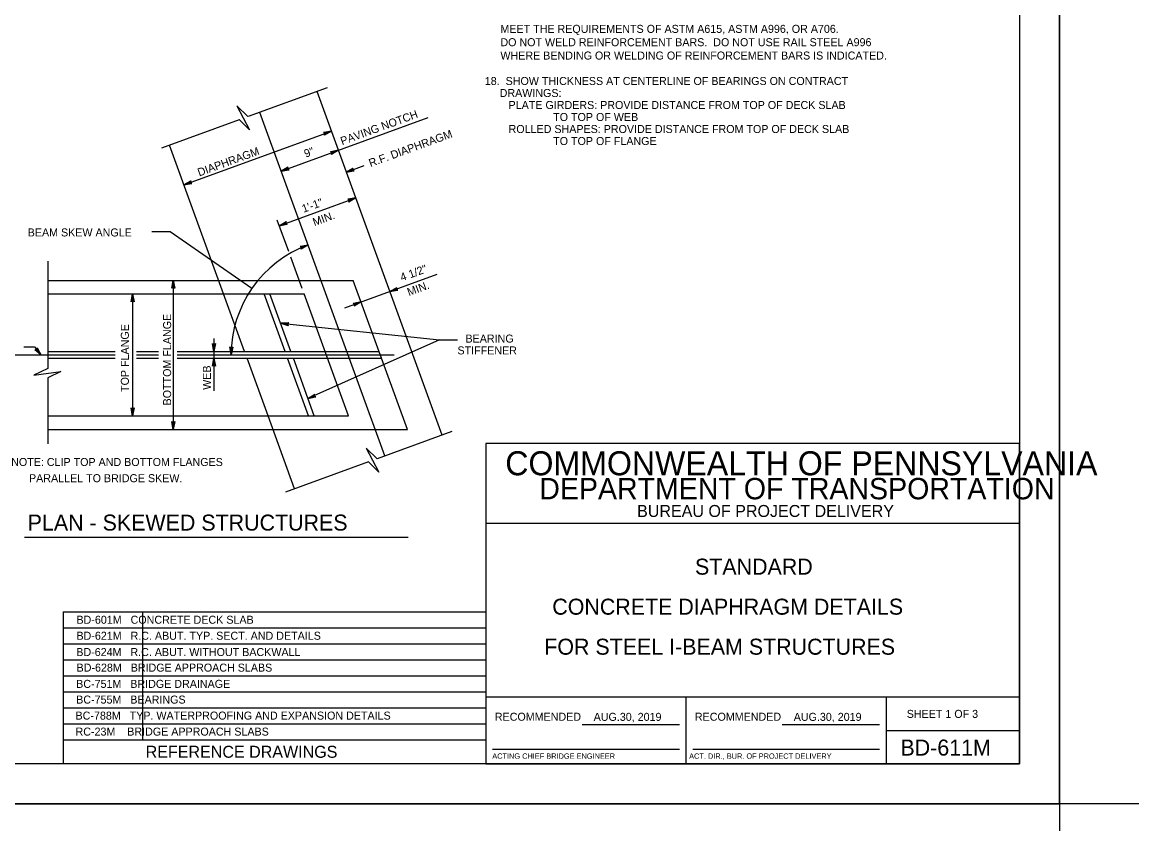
# Model space of a CAD drawing. Extents: x 640009 to 641706, y 298547 to 299735.
# Drawn here: x 640461.6 to 640877.6, y 299133.7 to 299434.1 of the extents above; entities that cross this region are included whole.
import ezdxf

# ---------------------------------------------------------------- set-up
doc = ezdxf.new("R2010")
doc.units = 0
doc.layers.add('1', color=7, linetype='Continuous')
doc.layers.add('PLT-BNDY', color=7, linetype='Continuous')

msp = doc.modelspace()

# ---------------------------------------------------------------- linework, layer by layer
at = {"layer": '1'}
for p, q in [((640835.47, 299720.17), (640835.47, 299156.17)), ((640835.47, 299720.17), (640835.47, 299156.17)), ((640576.01, 299409.55), (640546.3, 299398.74)), ((640619.01, 299279.35), (640572.14, 299408.14)), ((640597.53, 299271.53), (640550.66, 299400.32)), ((640542.93, 299397.51), (640513.87, 299386.93)), ((640558.67, 299378.31), (640613.85, 299398.39)), ((640522.26, 299373.17), (640577.54, 299393.29)), ((640537.14, 299332.28), (640516.86, 299388.02)), ((640583.14, 299377.91), (640589.88, 299380.37)), ((640558.01, 299357.83), (640586.65, 299368.26)), ((640561.54, 299348.14), (640557.26, 299359.9)), ((640510.22, 299355.67), (640517.07, 299355.67)), ((640517.07, 299355.67), (640547.76, 299334.38)), ((640566.57, 299334.31), (640562.29, 299346.07)), ((640471.19, 299344.51), (640471.19, 299304.37)), ((640471.19, 299337.36), (640585.73, 299337.36)), ((640518.25, 299337.36), (640518.25, 299281.48)), ((640582.58, 299327.02), (640617.22, 299339.63)), ((640606.07, 299281.48), (640585.73, 299337.36)), ((640471.19, 299332.28), (640567.31, 299332.28)), ((640503.01, 299332.28), (640503.01, 299286.56)), ((640545, 299310.69), (640537.14, 299332.28)), ((640560.21, 299310.69), (640552.36, 299332.28)), ((640562.34, 299310.69), (640554.48, 299332.28)), ((640583.95, 299286.56), (640567.31, 299332.28)), ((640558.49, 299321.27), (640618.01, 299315.12)), ((640462.19, 299312.44), (640466.19, 299312.44)), ((640466.19, 299312.44), (640468.66, 299309.42)), ((640533.49, 299315.6), (640533.49, 299295.92)), ((640618.01, 299315.12), (640568.76, 299293.07)), ((640618.01, 299315.12), (640624.86, 299315.12)), ((640446.9, 299309.42), (640496.46, 299309.42)), ((640471.19, 299310.69), (640496.46, 299310.69)), ((640471.19, 299308.15), (640496.46, 299308.15)), ((640504.48, 299310.69), (640512.71, 299310.69)), ((640504.48, 299309.42), (640512.71, 299309.42)), ((640504.48, 299308.15), (640512.71, 299308.15)), ((640519.73, 299310.69), (640575.17, 299310.69)), ((640519.73, 299309.42), (640601.1, 299309.42)), ((640519.73, 299308.15), (640576.09, 299308.15)), ((640553.79, 299286.56), (640545.93, 299308.15)), ((640569, 299286.56), (640561.14, 299308.15)), ((640571.13, 299286.56), (640563.27, 299308.15)), ((640575.17, 299310.69), (640595.44, 299310.69)), ((640576.09, 299308.15), (640596.37, 299308.15)), ((640471.19, 299300.85), (640471.19, 299276.08)), ((640471.19, 299286.56), (640583.95, 299286.56)), ((640563.73, 299259.23), (640553.79, 299286.56)), ((640471.19, 299281.48), (640606.07, 299281.48)), ((640622.74, 299280.71), (640594.72, 299270.51)), ((640835.47, 299276.17), (640635.47, 299276.17)), ((640635.47, 299276.17), (640635.47, 299156.17)), ((640835.47, 299276.17), (640635.47, 299276.17)), ((640635.47, 299276.17), (640635.47, 299156.17)), ((640835.47, 299156.17), (640835.47, 299276.17)), ((640835.47, 299156.17), (640835.47, 299276.17)), ((640591.41, 299269.31), (640560.39, 299258.01)), ((640835.47, 299246.17), (640635.47, 299246.17)), ((640835.47, 299246.17), (640635.47, 299246.17)), ((640462.55, 299241.16), (640606.33, 299241.16)), ((640477.04, 299213.17), (640477.04, 299156.17)), ((640477.04, 299213.17), (640635.47, 299213.17)), ((640506.91, 299165.17), (640506.91, 299213.17)), ((640477.04, 299207.17), (640635.47, 299207.17)), ((640477.04, 299201.17), (640635.47, 299201.17)), ((640477.04, 299195.17), (640635.47, 299195.17)), ((640477.04, 299189.17), (640635.47, 299189.17)), ((640477.04, 299183.17), (640635.47, 299183.17)), ((640835.47, 299181.17), (640635.47, 299181.17)), ((640835.47, 299181.17), (640635.47, 299181.17)), ((640710.47, 299156.17), (640710.47, 299181.17)), ((640785.47, 299181.17), (640785.47, 299156.17)), ((640785.47, 299181.17), (640785.47, 299156.17)), ((640477.04, 299177.17), (640635.47, 299177.17)), ((640477.04, 299171.17), (640635.47, 299171.17)), ((640671.56, 299170.89), (640707.97, 299170.89)), ((640746.56, 299170.89), (640782.97, 299170.89)), ((640785.47, 299168.67), (640835.47, 299168.67)), ((640785.47, 299168.67), (640835.47, 299168.67)), ((640477.04, 299165.17), (640635.47, 299165.17)), ((640637.97, 299161.67), (640707.97, 299161.67)), ((640712.97, 299161.67), (640782.97, 299161.67)), ((640835.47, 299156.17), (640049.47, 299156.17)), ((640835.47, 299156.17), (640049.47, 299156.17)), ((640635.47, 299156.17), (640835.47, 299156.17)), ((640635.47, 299156.17), (640835.47, 299156.17))]:
    msp.add_line(p, q, dxfattribs=at)
for points in [[(640546.21, 299398.83), (640542.05, 299402.83), (640546.82, 299393.77), (640542.9, 299397.62)], [(640577.54, 299393.29), (640574.93, 299391.74), (640575.01, 299391.85), (640575.09, 299391.97), (640575.11, 299392.08), (640575.14, 299392.2), (640575.12, 299392.3), (640575.1, 299392.4), (640575.05, 299392.48), (640575, 299392.57), (640574.91, 299392.65), (640574.82, 299392.72), (640574.68, 299392.76), (640574.55, 299392.79), (640577.54, 299393.29), (640574.68, 299392.76), (640574.82, 299392.72), (640577.54, 299393.29), (640574.91, 299392.65), (640575, 299392.57), (640577.54, 299393.29), (640575.05, 299392.48), (640575.1, 299392.4), (640577.54, 299393.29), (640575.12, 299392.3), (640575.14, 299392.2), (640577.54, 299393.29), (640575.11, 299392.08), (640575.09, 299391.97), (640577.54, 299393.29), (640575.01, 299391.85)], [(640580.15, 299386.12), (640577.54, 299384.58), (640577.62, 299384.69), (640577.7, 299384.81), (640577.72, 299384.92), (640577.74, 299385.04), (640577.72, 299385.14), (640577.71, 299385.24), (640577.66, 299385.32), (640577.61, 299385.41), (640577.52, 299385.49), (640577.43, 299385.56), (640577.29, 299385.59), (640577.16, 299385.63), (640580.15, 299386.12), (640577.29, 299385.59), (640577.43, 299385.56), (640580.15, 299386.12), (640577.52, 299385.49), (640577.61, 299385.41), (640580.15, 299386.12), (640577.66, 299385.32), (640577.71, 299385.24), (640580.15, 299386.12), (640577.72, 299385.14), (640577.74, 299385.04), (640580.15, 299386.12), (640577.72, 299384.92), (640577.7, 299384.81), (640580.15, 299386.12), (640577.62, 299384.69)], [(640558.67, 299378.31), (640561.28, 299379.85), (640561.2, 299379.74), (640561.12, 299379.62), (640561.1, 299379.51), (640561.07, 299379.4), (640561.09, 299379.3), (640561.11, 299379.2), (640561.16, 299379.11), (640561.21, 299379.02), (640561.3, 299378.95), (640561.39, 299378.87), (640561.53, 299378.84), (640561.66, 299378.8), (640558.67, 299378.31), (640561.53, 299378.84), (640561.39, 299378.87), (640558.67, 299378.31), (640561.3, 299378.95), (640561.21, 299379.02), (640558.67, 299378.31), (640561.16, 299379.11), (640561.11, 299379.2), (640558.67, 299378.31), (640561.09, 299379.3), (640561.07, 299379.4), (640558.67, 299378.31), (640561.1, 299379.51), (640561.12, 299379.62), (640558.67, 299378.31), (640561.2, 299379.74)], [(640583.14, 299377.91), (640585.75, 299379.46), (640585.67, 299379.35), (640585.59, 299379.23), (640585.57, 299379.12), (640585.54, 299379), (640585.56, 299378.9), (640585.58, 299378.8), (640585.63, 299378.72), (640585.68, 299378.63), (640585.77, 299378.55), (640585.86, 299378.48), (640586, 299378.44), (640586.13, 299378.41), (640583.14, 299377.91), (640586, 299378.44), (640585.86, 299378.48), (640583.14, 299377.91), (640585.77, 299378.55), (640585.68, 299378.63), (640583.14, 299377.91), (640585.63, 299378.72), (640585.58, 299378.8), (640583.14, 299377.91), (640585.56, 299378.9), (640585.54, 299379), (640583.14, 299377.91), (640585.57, 299379.12), (640585.59, 299379.23), (640583.14, 299377.91), (640585.67, 299379.35)], [(640522.26, 299373.17), (640524.88, 299374.71), (640524.8, 299374.6), (640524.71, 299374.48), (640524.69, 299374.37), (640524.67, 299374.25), (640524.69, 299374.15), (640524.71, 299374.05), (640524.76, 299373.97), (640524.81, 299373.88), (640524.9, 299373.8), (640524.99, 299373.73), (640525.12, 299373.7), (640525.26, 299373.66), (640522.26, 299373.17), (640525.12, 299373.7), (640524.99, 299373.73), (640522.26, 299373.17), (640524.9, 299373.8), (640524.81, 299373.88), (640522.26, 299373.17), (640524.76, 299373.97), (640524.71, 299374.05), (640522.26, 299373.17), (640524.69, 299374.15), (640524.67, 299374.25), (640522.26, 299373.17), (640524.69, 299374.37), (640524.71, 299374.48), (640522.26, 299373.17), (640524.8, 299374.6)], [(640586.65, 299368.26), (640584.04, 299366.71), (640584.12, 299366.83), (640584.2, 299366.94), (640584.22, 299367.06), (640584.25, 299367.17), (640584.23, 299367.27), (640584.21, 299367.37), (640584.16, 299367.46), (640584.11, 299367.55), (640584.02, 299367.62), (640583.93, 299367.69), (640583.79, 299367.73), (640583.66, 299367.76), (640586.65, 299368.26), (640583.79, 299367.73), (640583.93, 299367.69), (640586.65, 299368.26), (640584.02, 299367.62), (640584.11, 299367.55), (640586.65, 299368.26), (640584.16, 299367.46), (640584.21, 299367.37), (640586.65, 299368.26), (640584.23, 299367.27), (640584.25, 299367.17), (640586.65, 299368.26), (640584.22, 299367.06), (640584.2, 299366.94), (640586.65, 299368.26), (640584.12, 299366.83)], [(640558.01, 299357.83), (640560.62, 299359.38), (640560.54, 299359.27), (640560.46, 299359.15), (640560.44, 299359.04), (640560.42, 299358.92), (640560.44, 299358.82), (640560.45, 299358.72), (640560.5, 299358.63), (640560.55, 299358.55), (640560.64, 299358.47), (640560.73, 299358.4), (640560.87, 299358.36), (640561, 299358.33), (640558.01, 299357.83), (640560.87, 299358.36), (640560.73, 299358.4), (640558.01, 299357.83), (640560.64, 299358.47), (640560.55, 299358.55), (640558.01, 299357.83), (640560.5, 299358.63), (640560.45, 299358.72), (640558.01, 299357.83), (640560.44, 299358.82), (640560.42, 299358.92), (640558.01, 299357.83), (640560.44, 299359.04), (640560.46, 299359.15), (640558.01, 299357.83), (640560.54, 299359.27)], [(640568.76, 299350.57), (640566.15, 299349.03), (640566.23, 299349.14), (640566.31, 299349.26), (640566.33, 299349.37), (640566.35, 299349.48), (640566.34, 299349.58), (640566.32, 299349.68), (640566.27, 299349.77), (640566.22, 299349.86), (640566.13, 299349.93), (640566.04, 299350.01), (640565.9, 299350.04), (640565.77, 299350.08), (640568.76, 299350.57), (640565.9, 299350.04), (640566.04, 299350.01), (640568.76, 299350.57), (640566.13, 299349.93), (640566.22, 299349.86), (640568.76, 299350.57), (640566.27, 299349.77), (640566.32, 299349.68), (640568.76, 299350.57), (640566.34, 299349.58), (640566.35, 299349.48), (640568.76, 299350.57), (640566.33, 299349.37), (640566.31, 299349.26), (640568.76, 299350.57), (640566.23, 299349.14)], [(640518.25, 299337.36), (640518.81, 299334.38), (640518.73, 299334.49), (640518.65, 299334.61), (640518.55, 299334.67), (640518.45, 299334.73), (640518.35, 299334.74), (640518.25, 299334.76), (640518.15, 299334.74), (640518.05, 299334.73), (640517.95, 299334.67), (640517.85, 299334.61), (640517.77, 299334.49), (640517.69, 299334.38), (640518.25, 299337.36), (640517.77, 299334.49), (640517.85, 299334.61), (640518.25, 299337.36), (640517.95, 299334.67), (640518.05, 299334.73), (640518.25, 299337.36), (640518.15, 299334.74), (640518.25, 299334.76), (640518.25, 299337.36), (640518.35, 299334.74), (640518.45, 299334.73), (640518.25, 299337.36), (640518.55, 299334.67), (640518.65, 299334.61), (640518.25, 299337.36), (640518.73, 299334.49)], [(640599.43, 299333.15), (640602.04, 299334.7), (640601.96, 299334.59), (640601.88, 299334.47), (640601.86, 299334.36), (640601.84, 299334.24), (640601.85, 299334.14), (640601.87, 299334.04), (640601.92, 299333.96), (640601.97, 299333.87), (640602.06, 299333.79), (640602.15, 299333.72), (640602.29, 299333.68), (640602.42, 299333.65), (640599.43, 299333.15), (640602.29, 299333.68), (640602.15, 299333.72), (640599.43, 299333.15), (640602.06, 299333.79), (640601.97, 299333.87), (640599.43, 299333.15), (640601.92, 299333.96), (640601.87, 299334.04), (640599.43, 299333.15), (640601.85, 299334.14), (640601.84, 299334.24), (640599.43, 299333.15), (640601.86, 299334.36), (640601.88, 299334.47), (640599.43, 299333.15), (640601.96, 299334.59)], [(640503.01, 299332.28), (640503.57, 299329.3), (640503.49, 299329.42), (640503.41, 299329.53), (640503.31, 299329.59), (640503.21, 299329.65), (640503.11, 299329.67), (640503.01, 299329.68), (640502.91, 299329.67), (640502.81, 299329.65), (640502.71, 299329.59), (640502.61, 299329.53), (640502.53, 299329.42), (640502.45, 299329.3), (640503.01, 299332.28), (640502.53, 299329.42), (640502.61, 299329.53), (640503.01, 299332.28), (640502.71, 299329.59), (640502.81, 299329.65), (640503.01, 299332.28), (640502.91, 299329.67), (640503.01, 299329.68), (640503.01, 299332.28), (640503.11, 299329.67), (640503.21, 299329.65), (640503.01, 299332.28), (640503.31, 299329.59), (640503.41, 299329.53), (640503.01, 299332.28), (640503.49, 299329.42)], [(640588.69, 299329.25), (640586.08, 299327.7), (640586.16, 299327.81), (640586.24, 299327.93), (640586.26, 299328.04), (640586.28, 299328.16), (640586.26, 299328.26), (640586.25, 299328.36), (640586.19, 299328.44), (640586.14, 299328.53), (640586.05, 299328.61), (640585.96, 299328.68), (640585.83, 299328.72), (640585.69, 299328.75), (640588.69, 299329.25), (640585.83, 299328.72), (640585.96, 299328.68), (640588.69, 299329.25), (640586.05, 299328.61), (640586.14, 299328.53), (640588.69, 299329.25), (640586.19, 299328.44), (640586.25, 299328.36), (640588.69, 299329.25), (640586.26, 299328.26), (640586.28, 299328.16), (640588.69, 299329.25), (640586.26, 299328.04), (640586.24, 299327.93), (640588.69, 299329.25), (640586.16, 299327.81)], [(640558.49, 299321.27), (640561.52, 299321.48), (640561.4, 299321.41), (640561.27, 299321.34), (640561.2, 299321.25), (640561.13, 299321.16), (640561.11, 299321.06), (640561.08, 299320.96), (640561.08, 299320.86), (640561.09, 299320.76), (640561.13, 299320.66), (640561.18, 299320.55), (640561.29, 299320.46), (640561.39, 299320.37), (640558.49, 299321.27), (640561.29, 299320.46), (640561.18, 299320.55), (640558.49, 299321.27), (640561.13, 299320.66), (640561.09, 299320.76), (640558.49, 299321.27), (640561.08, 299320.86), (640561.08, 299320.96), (640558.49, 299321.27), (640561.11, 299321.06), (640561.13, 299321.16), (640558.49, 299321.27), (640561.2, 299321.25), (640561.27, 299321.34), (640558.49, 299321.27), (640561.4, 299321.41)], [(640468.66, 299309.42), (640466.34, 299311.37), (640466.47, 299311.34), (640466.61, 299311.3), (640466.72, 299311.31), (640466.84, 299311.33), (640466.93, 299311.38), (640467.01, 299311.43), (640467.08, 299311.51), (640467.15, 299311.59), (640467.19, 299311.69), (640467.23, 299311.8), (640467.22, 299311.94), (640467.2, 299312.08), (640468.66, 299309.42), (640467.22, 299311.94), (640467.23, 299311.8), (640468.66, 299309.42), (640467.19, 299311.69), (640467.15, 299311.59), (640468.66, 299309.42), (640467.08, 299311.51), (640467.01, 299311.43), (640468.66, 299309.42), (640466.93, 299311.38), (640466.84, 299311.33), (640468.66, 299309.42), (640466.72, 299311.31), (640466.61, 299311.3), (640468.66, 299309.42), (640466.47, 299311.34)], [(640533.49, 299310.69), (640532.93, 299313.67), (640533.01, 299313.56), (640533.09, 299313.44), (640533.19, 299313.38), (640533.29, 299313.33), (640533.39, 299313.31), (640533.49, 299313.29), (640533.59, 299313.31), (640533.69, 299313.33), (640533.79, 299313.38), (640533.89, 299313.44), (640533.97, 299313.56), (640534.05, 299313.67), (640533.49, 299310.69), (640533.97, 299313.56), (640533.89, 299313.44), (640533.49, 299310.69), (640533.79, 299313.38), (640533.69, 299313.33), (640533.49, 299310.69), (640533.59, 299313.31), (640533.49, 299313.29), (640533.49, 299310.69), (640533.39, 299313.31), (640533.29, 299313.33), (640533.49, 299310.69), (640533.19, 299313.38), (640533.09, 299313.44), (640533.49, 299310.69), (640533.01, 299313.56)], [(640539.95, 299309.42), (640539.48, 299312.42), (640539.55, 299312.3), (640539.63, 299312.18), (640539.73, 299312.12), (640539.82, 299312.06), (640539.92, 299312.04), (640540.02, 299312.02), (640540.12, 299312.03), (640540.22, 299312.05), (640540.33, 299312.1), (640540.43, 299312.16), (640540.51, 299312.27), (640540.59, 299312.38), (640539.95, 299309.42), (640540.51, 299312.27), (640540.43, 299312.16), (640539.95, 299309.42), (640540.33, 299312.1), (640540.22, 299312.05), (640539.95, 299309.42), (640540.12, 299312.03), (640540.02, 299312.02), (640539.95, 299309.42), (640539.92, 299312.04), (640539.82, 299312.06), (640539.95, 299309.42), (640539.73, 299312.12), (640539.63, 299312.18), (640539.95, 299309.42), (640539.55, 299312.3)], [(640533.49, 299308.15), (640534.05, 299305.17), (640533.97, 299305.28), (640533.89, 299305.4), (640533.79, 299305.46), (640533.69, 299305.51), (640533.59, 299305.53), (640533.49, 299305.55), (640533.39, 299305.53), (640533.29, 299305.51), (640533.19, 299305.46), (640533.09, 299305.4), (640533.01, 299305.28), (640532.93, 299305.17), (640533.49, 299308.15), (640533.01, 299305.28), (640533.09, 299305.4), (640533.49, 299308.15), (640533.19, 299305.46), (640533.29, 299305.51), (640533.49, 299308.15), (640533.39, 299305.53), (640533.49, 299305.55), (640533.49, 299308.15), (640533.59, 299305.53), (640533.69, 299305.51), (640533.49, 299308.15), (640533.79, 299305.46), (640533.89, 299305.4), (640533.49, 299308.15), (640533.97, 299305.28)], [(640471.19, 299304.37), (640466.01, 299301.83), (640476.15, 299303.21), (640471.19, 299300.85)], [(640568.76, 299293.07), (640571.3, 299294.73), (640571.22, 299294.61), (640571.15, 299294.49), (640571.13, 299294.38), (640571.11, 299294.26), (640571.14, 299294.16), (640571.16, 299294.06), (640571.21, 299293.98), (640571.27, 299293.89), (640571.36, 299293.82), (640571.45, 299293.75), (640571.59, 299293.72), (640571.73, 299293.69), (640568.76, 299293.07), (640571.59, 299293.72), (640571.45, 299293.75), (640568.76, 299293.07), (640571.36, 299293.82), (640571.27, 299293.89), (640568.76, 299293.07), (640571.21, 299293.98), (640571.16, 299294.06), (640568.76, 299293.07), (640571.14, 299294.16), (640571.11, 299294.26), (640568.76, 299293.07), (640571.13, 299294.38), (640571.15, 299294.49), (640568.76, 299293.07), (640571.22, 299294.61)], [(640503.01, 299286.56), (640502.45, 299289.54), (640502.53, 299289.42), (640502.61, 299289.31), (640502.71, 299289.25), (640502.81, 299289.19), (640502.91, 299289.17), (640503.01, 299289.16), (640503.11, 299289.17), (640503.21, 299289.19), (640503.31, 299289.25), (640503.41, 299289.31), (640503.49, 299289.42), (640503.57, 299289.54), (640503.01, 299286.56), (640503.49, 299289.42), (640503.41, 299289.31), (640503.01, 299286.56), (640503.31, 299289.25), (640503.21, 299289.19), (640503.01, 299286.56), (640503.11, 299289.17), (640503.01, 299289.16), (640503.01, 299286.56), (640502.91, 299289.17), (640502.81, 299289.19), (640503.01, 299286.56), (640502.71, 299289.25), (640502.61, 299289.31), (640503.01, 299286.56), (640502.53, 299289.42)], [(640518.25, 299281.48), (640517.69, 299284.46), (640517.77, 299284.35), (640517.85, 299284.23), (640517.95, 299284.17), (640518.05, 299284.11), (640518.15, 299284.1), (640518.25, 299284.08), (640518.35, 299284.1), (640518.45, 299284.11), (640518.55, 299284.17), (640518.65, 299284.23), (640518.73, 299284.35), (640518.81, 299284.46), (640518.25, 299281.48), (640518.73, 299284.35), (640518.65, 299284.23), (640518.25, 299281.48), (640518.55, 299284.17), (640518.45, 299284.11), (640518.25, 299281.48), (640518.35, 299284.1), (640518.25, 299284.08), (640518.25, 299281.48), (640518.15, 299284.1), (640518.05, 299284.11), (640518.25, 299281.48), (640517.95, 299284.17), (640517.85, 299284.23), (640518.25, 299281.48), (640517.77, 299284.35)], [(640594.72, 299270.51), (640590.56, 299274.51), (640595.33, 299265.45), (640591.41, 299269.31)]]:
    msp.add_lwpolyline(points, dxfattribs=at)
msp.add_arc((640583.74, 299309.42), 43.79, 110, 180, dxfattribs=at)
at = {"layer": 'PLT-BNDY'}
for points in [[(640009.47, 299735.17), (640850.47, 299735.17), (640850.47, 299141.17), (640009.47, 299141.17)], [(640850.47, 299735.17), (641691.47, 299735.17), (641691.47, 299141.17), (640850.47, 299141.17)], [(640009.47, 299141.17), (640850.47, 299141.17), (640850.47, 298547.17), (640009.47, 298547.17)]]:
    msp.add_lwpolyline(points, close=True, dxfattribs=at)

# ---------------------------------------------------------------- texts
at = {"layer": '1'}
for s, height, p in [('     MEET THE REQUIREMENTS OF ASTM A615, ASTM A996, OR A706.', 3, (640635.32, 299430.12)), ('     DO NOT WELD REINFORCEMENT BARS.  DO NOT USE RAIL STEEL A996', 3, (640635.32, 299425.12)), ('     WHERE BENDING OR WELDING OF REINFORCEMENT BARS IS INDICATED.', 3, (640635.32, 299420.12)), ('18.  SHOW THICKNESS AT CENTERLINE OF BEARINGS ON CONTRACT', 3, (640635.04, 299410.59)), ('     DRAWINGS:', 3, (640635.04, 299406.09)), ('        PLATE GIRDERS: PROVIDE DISTANCE FROM TOP OF DECK SLAB', 3, (640635.04, 299401.59)), ('                       TO TOP OF WEB', 3, (640635.04, 299397.09)), ('        ROLLED SHAPES: PROVIDE DISTANCE FROM TOP OF DECK SLAB', 3, (640635.04, 299392.59)), ('                       TO TOP OF FLANGE', 3, (640635.04, 299388.09)), ('BEAM SKEW ANGLE', 3, (640463.69, 299353.82)), ('BEARING', 3, (640627.8, 299314.04)), ('STIFFENER', 3, (640624.8, 299309.6)), ('NOTE: CLIP TOP AND BOTTOM FLANGES', 3, (640457.49, 299267.78)), ('COMMONWEALTH OF PENNSYLVANIA', 9, (640642.72, 299264.3)), ('      PARALLEL TO BRIDGE SKEW.', 3, (640457.49, 299261.71)), ('DEPARTMENT OF TRANSPORTATION', 8.0002, (640655.47, 299255.3)), ('PLAN - SKEWED STRUCTURES', 6, (640463.68, 299243.57)), ('BUREAU OF PROJECT DELIVERY', 4.5, (640692.13, 299248.67)), ('STANDARD', 6, (640713.84, 299227.05)), ('CONCRETE DIAPHRAGM DETAILS', 6, (640660.34, 299212.05)), ('BD-601M   CONCRETE DECK SLAB', 3, (640481.97, 299208.66)), ('BD-621M   R.C. ABUT. TYP. SECT. AND DETAILS', 3, (640481.97, 299202.66)), ('BD-624M   R.C. ABUT. WITHOUT BACKWALL', 3, (640481.91, 299196.55)), ('FOR STEEL I-BEAM STRUCTURES', 6, (640657.34, 299197.05)), ('BD-628M   BRIDGE APPROACH SLABS', 3, (640482.01, 299190.71)), ('BC-751M   BRIDGE DRAINAGE', 3, (640481.86, 299184.62)), ('BC-755M   BEARINGS', 3, (640481.86, 299178.73)), ('BC-788M   TYP. WATERPROOFING AND EXPANSION DETAILS', 3, (640481.62, 299172.73)), ('RECOMMENDED', 3, (640638.8, 299172.3)), ('AUG.30, 2019', 3, (640675.85, 299172.26)), ('RECOMMENDED', 3, (640713.8, 299172.3)), ('AUG.30, 2019', 3, (640750.85, 299172.26)), ('SHEET 1 OF 3', 3, (640793.21, 299173.37)), ('RC-23M    BRIDGE APPROACH SLABS', 3, (640481.62, 299166.73)), ('REFERENCE DRAWINGS', 4.5, (640507.91, 299158.42)), ('BD-611M', 6, (640790.86, 299159.24)), ('ACTING CHIEF BRIDGE ENGINEER', 2.0002, (640637.84, 299158.05)), (' ACT. DIR., BUR. OF PROJECT DELIVERY', 2.0002, (640710.87, 299158.05))]:
    msp.add_text(s, height=height, dxfattribs=at).set_placement(p)
for s, rotation, p in [('PAVING NOTCH', 20, (640581.56, 299388.01)), ('R.F. DIAPHRAGM', 20, (640592.2, 299379.79)), (' DIAPHRAGM', 20, (640526.95, 299375.9)), ('9"', 20, (640567.93, 299383.32)), ('1\'-1"', 20, (640567.11, 299362.66)), ('MIN.', 20, (640571.16, 299357.67)), ('4 1/2"', 20, (640603.94, 299336.96)), ('MIN.', 20, (640606.58, 299331.46)), ('BOTTOM FLANGE', 90, (640517.45, 299290.49)), ('TOP FLANGE', 90, (640501.61, 299295.54)), ('WEB', 90, (640532.34, 299296.33))]:
    msp.add_text(s, height=3, rotation=rotation, dxfattribs=at).set_placement(p)

doc.saveas('drawing.dxf')
